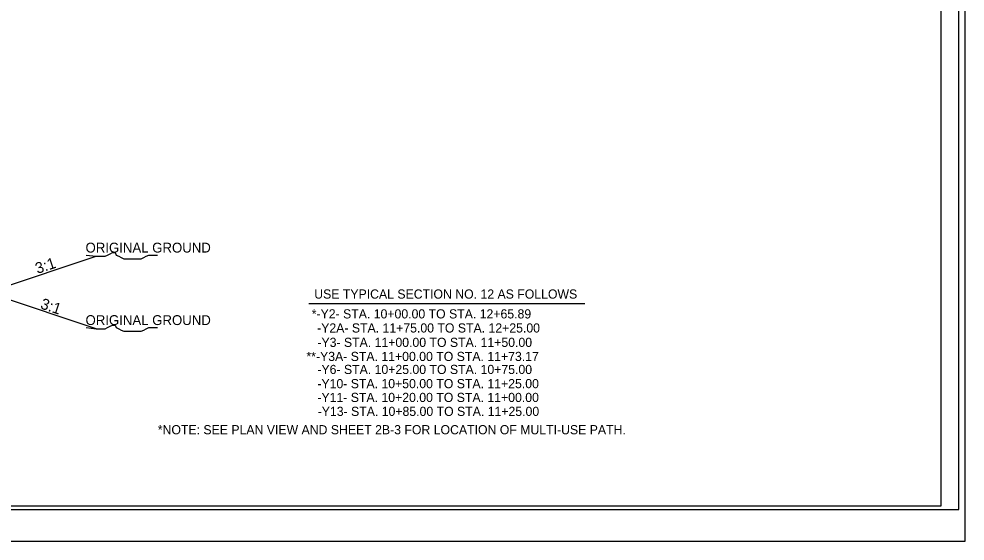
# Model space of a CAD drawing. Extents: x 958711 to 962106, y 831169 to 840840.
# Drawn here: x 959723 to 960395, y 834842 to 835213 of the extents above; entities that cross this region are included whole.
import ezdxf

# ---------------------------------------------------------------- set-up
doc = ezdxf.new("R2010")
doc.units = 0
for name, color, linetype in [('Old_Level_1', 7, 'Continuous'), ('Old_Level_21', 7, 'Continuous'), ('Old_Level_3', 7, 'Continuous'), ('Sheet Plot Border Inside CELL', 7, 'Continuous'), ('Sheet Plot Border Outside CELL', 7, 'Continuous'), ('Sheet Typical CELL', 7, 'Continuous')]:
    doc.layers.add(name, color=color, linetype=linetype)

msp = doc.modelspace()

# ---------------------------------------------------------------- linework, layer by layer
at = {"layer": 'Old_Level_1'}
for p, q in [((959700.88, 835018.94), (959778.06, 835044.67)), ((959778.06, 834993.21), (959700.88, 835018.94)), ((959928.85, 835011.09), (960124.79, 835011.09))]:
    msp.add_line(p, q, dxfattribs=at)
at = {"layer": 'Old_Level_21'}
for points in [[(959770.97, 835045.55), (959778.06, 835044.67), (959779.84, 835044.67), (959782.5, 835044.67), (959784.27, 835044.67), (959786.04, 835045.55), (959787.82, 835046.45), (959789.59, 835047.33), (959791.37, 835047.33), (959792.26, 835045.55), (959794.03, 835044.67), (959795.8, 835043.77), (959797.57, 835042.9), (959799.35, 835042.9), (959801.12, 835042.9), (959802.9, 835042.9), (959804.67, 835042.9), (959806.44, 835042.9), (959808.21, 835042.9), (959809.99, 835042.9), (959811.76, 835043.77), (959813.53, 835044.67), (959815.3, 835045.55), (959817.97, 835045.55), (959819.74, 835045.55), (959821.52, 835045.55)], [(959770.97, 834994.09), (959778.06, 834993.21), (959779.84, 834993.21), (959782.5, 834993.21), (959784.27, 834993.21), (959786.04, 834994.09), (959787.82, 834994.98), (959789.59, 834995.86), (959791.37, 834995.86), (959792.26, 834994.09), (959794.03, 834993.21), (959795.8, 834992.31), (959797.57, 834991.44), (959799.35, 834991.44), (959801.12, 834991.44), (959802.9, 834991.44), (959804.67, 834991.44), (959806.44, 834991.44), (959808.21, 834991.44), (959809.99, 834991.44), (959811.76, 834992.31), (959813.53, 834993.21), (959815.3, 834994.09), (959817.97, 834994.09), (959819.74, 834994.09), (959821.52, 834994.09)]]:
    msp.add_lwpolyline(points, dxfattribs=at)
at = {"layer": 'Sheet Plot Border Inside CELL'}
msp.add_lwpolyline([(960390.3, 835919.97), (958723.8, 835919.97), (958723.8, 834864.87), (960390.3, 834864.87)], close=True, dxfattribs=at)
at = {"layer": 'Sheet Plot Border Outside CELL'}
msp.add_lwpolyline([(960394.8, 835942.42), (958710.8, 835942.42), (958710.8, 834842.42), (960394.8, 834842.42)], close=True, dxfattribs=at)
at = {"layer": 'Sheet Typical CELL'}
msp.add_lwpolyline([(960377.8, 835917.42), (958877.8, 835917.42), (958877.8, 834867.42), (960377.8, 834867.42)], close=True, dxfattribs=at)

# ---------------------------------------------------------------- texts
at = {"layer": 'Old_Level_1'}
for s, p in [('USE TYPICAL SECTION NO. 12 AS FOLLOWS', (959932.79, 835014.61)), ('*-Y2- STA. 10+00.00 TO STA. 12+65.89', (959931, 835000.52)), ('-Y2A- STA. 11+75.00 TO STA. 12+25.00', (959934.83, 834990.52)), ('-Y3- STA. 11+00.00 TO STA. 11+50.00', (959935.02, 834980.29)), ('**-Y3A- STA. 11+00.00 TO STA. 11+73.17', (959927.24, 834970.29)), ('-Y6- STA. 10+25.00 TO STA. 10+75.00', (959935.02, 834961.05)), ('-Y10- STA. 10+50.00 TO STA. 11+25.00', (959935.02, 834950.98)), ('-Y11- STA. 10+20.00 TO STA. 11+00.00', (959935.02, 834941.18)), ('-Y13- STA. 10+85.00 TO STA. 11+25.00', (959935.22, 834931.28)), ('*NOTE: SEE PLAN VIEW AND SHEET 2B-3 FOR LOCATION OF MULTI-USE PATH.', (959821.72, 834918.26))]:
    msp.add_text(s, height=6.5088, dxfattribs=at).set_placement(p)
at = {"layer": 'Old_Level_21'}
for p in [(959770.43, 835047.3), (959770.43, 834995.84)]:
    msp.add_text('ORIGINAL GROUND', height=7, dxfattribs=at).set_placement(p)
at = {"layer": 'Old_Level_3'}
for rotation, p in [(18.43843, (959736.28, 835032.1)), (341.56157, (959737.87, 835007.77))]:
    msp.add_text('3:1', height=7.801, rotation=rotation, dxfattribs=at).set_placement(p)

doc.saveas('drawing.dxf')
